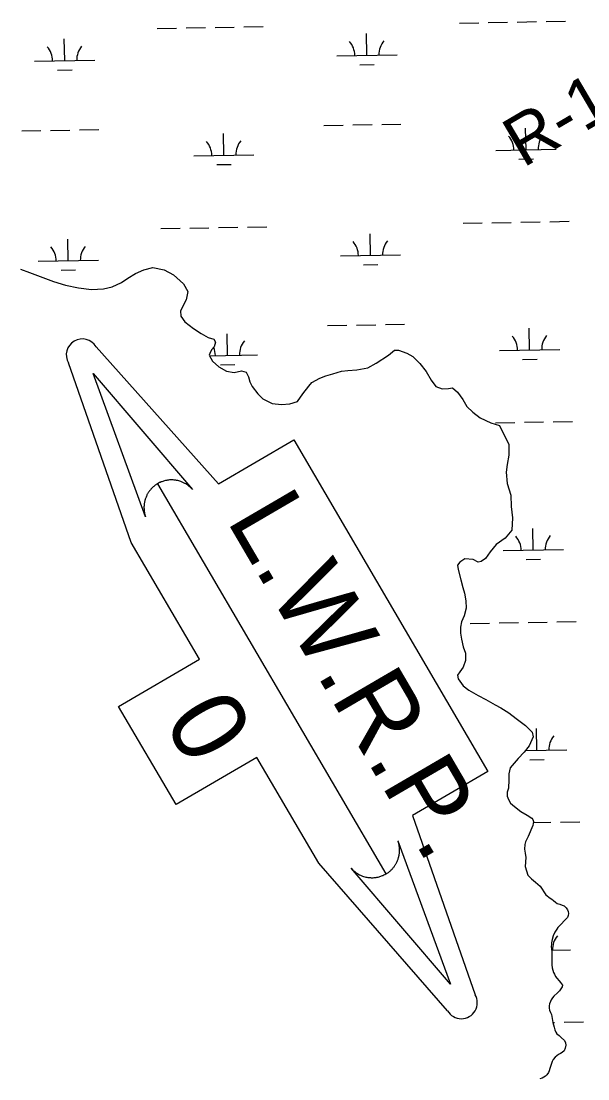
# Model space of a CAD drawing. Extents: x 3914892 to 3953151, y 242587 to 268572.
# Drawn here: x 3938068 to 3939009, y 249387 to 251144 of the extents above; entities that cross this region are included whole.
import ezdxf

# ---------------------------------------------------------------- set-up
doc = ezdxf.new("R2010")
doc.units = 0
for name, color, linetype in [('V-RIVR-RANG-IDEN', 7, 'Continuous'), ('V-TOPO-WATR-IDEN', 7, 'Continuous'), ('V-WETL-SWMP', 7, 'Continuous')]:
    doc.layers.add(name, color=color, linetype=linetype)

msp = doc.modelspace()

# ---------------------------------------------------------------- linework, layer by layer
at = {"layer": 'V-TOPO-WATR-IDEN'}
msp.add_line((3938294.2, 250375.8), (3938673.3, 249727.2), dxfattribs=at)
for points in [[(3938191.9, 250603.2), (3938395.4, 250375.4), (3938520.4, 250448.4), (3938842.6, 249897.2), (3938717.6, 249824.1), (3938821.3, 249526.5)], [(3938775.5, 249499.8), (3938561.7, 249745.3), (3938459.1, 249920.9), (3938325, 249842.5), (3938229.5, 250005.7), (3938363.6, 250084.1), (3938250.2, 250278.2), (3938146.2, 250576.5)]]:
    msp.add_lwpolyline(points, dxfattribs=at)
for points in [[(3938274.3, 250320.7), (3938187, 250559.1), (3938352, 250366.1), (3938348.8, 250369.4), (3938345.5, 250372.3), (3938344.1, 250373.3), (3938342.8, 250374.2), (3938341.2, 250375.3), (3938339.6, 250376.2), (3938338.2, 250376.9), (3938336.3, 250377.9), (3938334.1, 250378.8), (3938332.9, 250379.3), (3938331.3, 250379.8), (3938329.2, 250380.4), (3938327.5, 250380.8), (3938325.7, 250381.2), (3938324.5, 250381.4), (3938323.2, 250381.6), (3938321.5, 250381.8), (3938320, 250381.9), (3938318.5, 250382), (3938317.3, 250382), (3938315.5, 250382), (3938313.7, 250381.9), (3938312.3, 250381.7), (3938310.7, 250381.5), (3938309.3, 250381.3), (3938308, 250381.1), (3938307.1, 250380.9), (3938305.6, 250380.5), (3938304.1, 250380.1), (3938302.7, 250379.6), (3938301.3, 250379.1), (3938300, 250378.6), (3938298.6, 250378), (3938297.5, 250377.5), (3938295.9, 250376.7), (3938294.2, 250375.8), (3938293.6, 250375.4), (3938292.8, 250374.9), (3938291.9, 250374.3), (3938291, 250373.7), (3938290.2, 250373.1), (3938289.4, 250372.5), (3938288.5, 250371.8), (3938287.8, 250371.3), (3938286.9, 250370.5), (3938286.1, 250369.7), (3938285.5, 250369.2), (3938284.1, 250367.7), (3938283.3, 250366.9), (3938282.8, 250366.4), (3938282.1, 250365.5), (3938281.4, 250364.6), (3938280.7, 250363.7), (3938279.9, 250362.6), (3938279.2, 250361.6), (3938278.6, 250360.7), (3938278.2, 250360), (3938277.6, 250359.1), (3938277.1, 250358.2), (3938276.5, 250357.1), (3938276, 250356), (3938275.5, 250354.9), (3938274.9, 250353.5), (3938274.5, 250352.4), (3938274.1, 250351.3), (3938273.7, 250350.1), (3938273.4, 250349.2), (3938273.1, 250348.2), (3938272.7, 250346.7), (3938272.7, 250346.6), (3938272.5, 250345.7), (3938272.4, 250345), (3938272.2, 250344), (3938272, 250342.7), (3938271.8, 250341.7), (3938271.7, 250340.8), (3938271.6, 250339.6), (3938271.6, 250338.5), (3938271.5, 250337.7), (3938271.5, 250336.6), (3938271.5, 250335.2), (3938271.6, 250334.3), (3938271.6, 250333.6), (3938271.6, 250333), (3938271.7, 250332.3), (3938271.8, 250331.3), (3938271.9, 250330.3), (3938272, 250329.3), (3938272.2, 250328.4), (3938272.4, 250327.2), (3938272.6, 250326.4), (3938272.9, 250325.3), (3938273.2, 250323.9), (3938273.5, 250322.9), (3938273.7, 250322.2), (3938274, 250321.5), (3938274.1, 250321)], [(3938693.2, 249782.3), (3938780.5, 249543.9), (3938615.5, 249736.9), (3938618.6, 249733.6), (3938622, 249730.7), (3938623.4, 249729.6), (3938624.7, 249728.7), (3938626.3, 249727.7), (3938627.9, 249726.8), (3938629.3, 249726), (3938631.2, 249725.1), (3938633.3, 249724.2), (3938634.6, 249723.7), (3938636.2, 249723.2), (3938638.3, 249722.5), (3938639.9, 249722.1), (3938641.8, 249721.8), (3938643, 249721.5), (3938644.3, 249721.4), (3938645.9, 249721.2), (3938647.4, 249721.1), (3938648.9, 249721), (3938650.2, 249721), (3938652, 249721), (3938653.7, 249721.1), (3938655.1, 249721.2), (3938656.8, 249721.4), (3938658.2, 249721.7), (3938659.4, 249721.9), (3938660.4, 249722.1), (3938661.9, 249722.5), (3938663.4, 249722.9), (3938664.8, 249723.3), (3938666.2, 249723.8), (3938667.4, 249724.4), (3938668.8, 249724.9), (3938670, 249725.5), (3938671.5, 249726.3), (3938673.3, 249727.2), (3938673.8, 249727.5), (3938674.6, 249728), (3938675.5, 249728.6), (3938676.4, 249729.2), (3938677.3, 249729.8), (3938678.1, 249730.4), (3938679, 249731.2), (3938679.6, 249731.7), (3938680.6, 249732.5), (3938681.4, 249733.3), (3938682, 249733.8), (3938683.4, 249735.2), (3938684.1, 249736), (3938684.6, 249736.6), (3938685.4, 249737.5), (3938686.1, 249738.4), (3938686.8, 249739.3), (3938687.6, 249740.4), (3938688.3, 249741.4), (3938688.8, 249742.2), (3938689.3, 249742.9), (3938689.9, 249743.9), (3938690.4, 249744.8), (3938690.9, 249745.9), (3938691.4, 249747), (3938692, 249748.1), (3938692.6, 249749.5), (3938693, 249750.5), (3938693.4, 249751.7), (3938693.8, 249752.8), (3938694.1, 249753.8), (3938694.3, 249754.8), (3938694.7, 249756.3), (3938694.7, 249756.4), (3938694.9, 249757.3), (3938695.1, 249757.9), (3938695.3, 249759), (3938695.5, 249760.2), (3938695.6, 249761.2), (3938695.7, 249762.2), (3938695.8, 249763.3), (3938695.9, 249764.5), (3938695.9, 249765.3), (3938695.9, 249766.3), (3938695.9, 249767.8), (3938695.9, 249768.7), (3938695.9, 249769.3), (3938695.8, 249770), (3938695.8, 249770.7), (3938695.7, 249771.7), (3938695.5, 249772.7), (3938695.4, 249773.6), (3938695.3, 249774.6), (3938695, 249775.8), (3938694.9, 249776.5), (3938694.6, 249777.7), (3938694.2, 249779), (3938694, 249780), (3938693.7, 249780.8), (3938693.5, 249781.5), (3938693.3, 249782)]]:
    msp.add_lwpolyline(points, close=True, dxfattribs=at)
for centre, start, end in [((3938169, 250589.8), 30.308, 210.308), ((3938798.4, 249513.1), 210.308, 30.308)]:
    msp.add_arc(centre, 26.5, start, end, dxfattribs=at)
at = {"layer": 'V-WETL-SWMP'}
for p, q in [((3938293.5, 251132.3), (3938325.5, 251132.9)), ((3938341.5, 251133.2), (3938373.5, 251133.7)), ((3938389.5, 251134), (3938421.5, 251134.6)), ((3938437.5, 251134.9), (3938469.5, 251135.5)), ((3938795.3, 251141.3), (3938827.3, 251141.9)), ((3938843.3, 251142.1), (3938875.3, 251142.7)), ((3938891.3, 251143), (3938923.3, 251143.6)), ((3938939.3, 251143.9), (3938971.3, 251144.4)), ((3938139.9, 251078.8), (3938139.2, 251114.8)), ((3938641.7, 251087.8), (3938641, 251123.8)), ((3938089.9, 251077.9), (3938189.8, 251079.7)), ((3938591.7, 251086.9), (3938691.7, 251088.7)), ((3938128.1, 251063.2), (3938152.1, 251063.6)), ((3938630, 251072.1), (3938654, 251072.6)), ((3938570.4, 250971.1), (3938602.3, 250971.6)), ((3938618.3, 250971.9), (3938650.3, 250972.5)), ((3938666.3, 250972.8), (3938698.3, 250973.4)), ((3938068.5, 250962.1), (3938100.5, 250962.7)), ((3938116.5, 250962.9), (3938148.5, 250963.5)), ((3938164.5, 250963.8), (3938196.5, 250964.4)), ((3938404.1, 250921.7), (3938403.5, 250957.6)), ((3938906, 250930.6), (3938905.3, 250966.6)), ((3938354.2, 250920.8), (3938454.1, 250922.5)), ((3938856, 250929.7), (3938956, 250931.5)), ((3938392.4, 250906), (3938416.4, 250906.4)), ((3938894.2, 250915), (3938918.2, 250915.4)), ((3938299.5, 250799.7), (3938331.5, 250800.3)), ((3938347.5, 250800.5), (3938379.5, 250801.1)), ((3938395.4, 250801.4), (3938427.4, 250802)), ((3938443.4, 250802.3), (3938475.4, 250802.8)), ((3938801.3, 250808.7), (3938833.3, 250809.2)), ((3938849.3, 250809.5), (3938881.3, 250810.1)), ((3938897.3, 250810.4), (3938929.3, 250811)), ((3938945.3, 250811.2), (3938977.3, 250811.8)), ((3938145.8, 250746.2), (3938145.2, 250782.2)), ((3938647.6, 250755.2), (3938647, 250791.2)), ((3938095.8, 250745.3), (3938195.8, 250747.1)), ((3938597.6, 250754.3), (3938697.6, 250756.1)), ((3938066.7, 250732.1), (3938081.5, 250727)), ((3938081.5, 250727), (3938099.2, 250720.3)), ((3938134.1, 250730.5), (3938158.1, 250731)), ((3938244.8, 250717.2), (3938257.7, 250725.2)), ((3938257.7, 250725.2), (3938271.1, 250731)), ((3938271.1, 250731), (3938286.2, 250734.9)), ((3938286.2, 250734.9), (3938304.8, 250731.4)), ((3938304.8, 250731.4), (3938320.6, 250723.1)), ((3938635.9, 250739.5), (3938659.9, 250740)), ((3938099.2, 250720.3), (3938121.3, 250711.7)), ((3938121.3, 250711.7), (3938141.2, 250705.7)), ((3938218.6, 250703), (3938234, 250710.1)), ((3938234, 250710.1), (3938244.8, 250717.2)), ((3938320.6, 250723.1), (3938337, 250708.1)), ((3938337, 250708.1), (3938344.4, 250695.3)), ((3938141.2, 250705.7), (3938162.7, 250701.2)), ((3938162.7, 250701.2), (3938184.6, 250698.7)), ((3938184.6, 250698.7), (3938204.5, 250699.7)), ((3938204.5, 250699.7), (3938218.6, 250703)), ((3938344.4, 250695.3), (3938341.8, 250681.2)), ((3938341.8, 250681.2), (3938332.3, 250663.2)), ((3938332.3, 250663.2), (3938332.9, 250653.9)), ((3938332.9, 250653.9), (3938339.4, 250644.9)), ((3938339.4, 250644.9), (3938353.8, 250633.7)), ((3938576.3, 250638.4), (3938608.3, 250639)), ((3938624.3, 250639.3), (3938656.3, 250639.9)), ((3938672.3, 250640.2), (3938704.3, 250640.7)), ((3938353.8, 250633.7), (3938366.4, 250625.4)), ((3938366.4, 250625.4), (3938377.9, 250618.7)), ((3938410.1, 250589), (3938409.5, 250625)), ((3938911.9, 250598), (3938911.3, 250634)), ((3938377.9, 250618.7), (3938387.3, 250615.8)), ((3938388.3, 250603.3), (3938383.8, 250598.2)), ((3938387.3, 250615.8), (3938390.5, 250611)), ((3938390.5, 250611), (3938388.3, 250603.3)), ((3938380.9, 250592.1), (3938379.9, 250589.5)), ((3938379.9, 250589.5), (3938385.4, 250579.6)), ((3938380.5, 250588.5), (3938460.1, 250589.9)), ((3938383.8, 250598.2), (3938380.9, 250592.1)), ((3938657.2, 250576.1), (3938677.3, 250589.2)), ((3938677.3, 250589.2), (3938687.6, 250597.8)), ((3938687.6, 250597.8), (3938693.9, 250597.9)), ((3938693.9, 250597.9), (3938707.9, 250592.8)), ((3938707.9, 250592.8), (3938717.8, 250587.2)), ((3938717.8, 250587.2), (3938729.7, 250575.4)), ((3938861.9, 250597.1), (3938961.9, 250598.9)), ((3938385.4, 250579.6), (3938395.7, 250570)), ((3938395.7, 250570), (3938408.6, 250562.6)), ((3938398.4, 250573.4), (3938422.4, 250573.8)), ((3938625.2, 250565), (3938643.1, 250568.4)), ((3938643.1, 250568.4), (3938657.2, 250576.1)), ((3938729.7, 250575.4), (3938740, 250562.1)), ((3938900.2, 250582.4), (3938924.2, 250582.8)), ((3938408.6, 250562.6), (3938421.4, 250560.7)), ((3938421.4, 250560.7), (3938433.6, 250563.3)), ((3938433.6, 250563.3), (3938441.3, 250561.1)), ((3938441.3, 250561.1), (3938445.2, 250553.4)), ((3938445.2, 250553.4), (3938447.1, 250545.1)), ((3938550.5, 250543.8), (3938563.4, 250551.3)), ((3938563.4, 250551.3), (3938573.6, 250554.8)), ((3938573.6, 250554.8), (3938585.2, 250558.5)), ((3938585.2, 250558.5), (3938599.5, 250563)), ((3938599.5, 250563), (3938609.8, 250563.9)), ((3938609.8, 250563.9), (3938625.2, 250565)), ((3938740, 250562.1), (3938748.3, 250548)), ((3938447.1, 250545.1), (3938451.3, 250537.2)), ((3938451.3, 250537.2), (3938460.8, 250525.1)), ((3938535.2, 250524.9), (3938545.5, 250538.1)), ((3938545.5, 250538.1), (3938550.5, 250543.8)), ((3938748.3, 250548), (3938756.3, 250537.4)), ((3938756.3, 250537.4), (3938766.8, 250533.5)), ((3938766.8, 250533.5), (3938777, 250534.1)), ((3938777, 250534.1), (3938783.8, 250534.9)), ((3938783.8, 250534.9), (3938792.2, 250527.7)), ((3938460.8, 250525.1), (3938469.1, 250516.6)), ((3938469.1, 250516.6), (3938484.4, 250509.2)), ((3938526.3, 250512.5), (3938535.2, 250524.9)), ((3938792.2, 250527.7), (3938800.9, 250515.8)), ((3938800.9, 250515.8), (3938807.6, 250504.2)), ((3938484.4, 250509.2), (3938500, 250507.1)), ((3938500, 250507.1), (3938513.8, 250508.3)), ((3938513.8, 250508.3), (3938526.3, 250512.5)), ((3938807.6, 250504.2), (3938817.6, 250494.8)), ((3938817.6, 250494.8), (3938830, 250485.2)), ((3938830, 250485.2), (3938847.7, 250476.9)), ((3938951.2, 250478.6), (3938983.2, 250479.2)), ((3938847.7, 250476.9), (3938862.1, 250472.3)), ((3938855.2, 250476.9), (3938887.2, 250477.5)), ((3938862.1, 250472.3), (3938877.6, 250440.9)), ((3938903.2, 250477.8), (3938935.2, 250478.3)), ((3938877.6, 250440.9), (3938877.5, 250422.9)), ((3938877.5, 250422.9), (3938874.7, 250407.9)), ((3938874.7, 250407.9), (3938872.9, 250394.9)), ((3938872.9, 250394.9), (3938874.7, 250375.9)), ((3938874.7, 250375.9), (3938880.6, 250356.8)), ((3938880.6, 250356.8), (3938881.3, 250337.8)), ((3938881.3, 250337.8), (3938883.3, 250318.9)), ((3938883.3, 250318.9), (3938882.1, 250298.7)), ((3938871.5, 250285.5), (3938856.1, 250274.5)), ((3938882.1, 250298.7), (3938871.5, 250285.5)), ((3938917.9, 250265.4), (3938917.2, 250301.4)), ((3938856.1, 250274.5), (3938846.2, 250262.3)), ((3938804.5, 250250.7), (3938795.9, 250245.5)), ((3938818.3, 250249.7), (3938804.5, 250250.7)), ((3938838.5, 250251.4), (3938831.2, 250246.2)), ((3938846.2, 250262.3), (3938838.5, 250251.4)), ((3938867.9, 250264.5), (3938967.9, 250266.3)), ((3938795.9, 250245.5), (3938792.4, 250240.6)), ((3938792.4, 250240.6), (3938793, 250232.9)), ((3938793, 250232.9), (3938797.4, 250216)), ((3938826.4, 250245.6), (3938818.3, 250249.7)), ((3938831.2, 250246.2), (3938826.4, 250245.6)), ((3938906.2, 250249.7), (3938930.1, 250250.2)), ((3938797.4, 250216), (3938801, 250203)), ((3938801, 250203), (3938803.9, 250193.7)), ((3938803.9, 250193.7), (3938805.9, 250180.9)), ((3938805.9, 250180.9), (3938806.5, 250169)), ((3938806.5, 250169), (3938803, 250156.2)), ((3938798.9, 250146.2), (3938797.3, 250137.6)), ((3938803, 250156.2), (3938798.9, 250146.2)), ((3938861.2, 250144.3), (3938893.2, 250144.9)), ((3938909.2, 250145.1), (3938941.2, 250145.7)), ((3938957.2, 250146), (3938989.2, 250146.6)), ((3938797.3, 250137.6), (3938797.3, 250127.6)), ((3938797.3, 250127.6), (3938798.7, 250117.4)), ((3938813.2, 250143.4), (3938845.2, 250144)), ((3938798.7, 250117.4), (3938801.6, 250104.8)), ((3938801.6, 250104.8), (3938805.5, 250094.3)), ((3938805.5, 250094.3), (3938805.5, 250081.8)), ((3938805.5, 250081.8), (3938801.7, 250070.8)), ((3938795.9, 250063.1), (3938792.1, 250057.5)), ((3938792.1, 250057.5), (3938793.4, 250051.7)), ((3938801.7, 250070.8), (3938795.9, 250063.1)), ((3938793.4, 250051.7), (3938801.4, 250039.8)), ((3938801.4, 250039.8), (3938810.7, 250032.8)), ((3938810.7, 250032.8), (3938826.5, 250023.9)), ((3938826.5, 250023.9), (3938839.3, 250017.2)), ((3938839.3, 250017.2), (3938854.8, 250008.5)), ((3938854.8, 250008.5), (3938864.1, 250003.4)), ((3938864.1, 250003.4), (3938877.3, 249994.8)), ((3938877.3, 249994.8), (3938889.8, 249985.5)), ((3938889.8, 249985.5), (3938904.9, 249974)), ((3938904.9, 249974), (3938915.9, 249963.1)), ((3938917.5, 249955.1), (3938911.4, 249940.3)), ((3938915.9, 249963.1), (3938917.5, 249955.1)), ((3938923.8, 249932.8), (3938923.2, 249968.8)), ((3938911.4, 249940.3), (3938902.8, 249929.4)), ((3938892.6, 249919.1), (3938886.2, 249911.4)), ((3938902.8, 249929.4), (3938892.6, 249919.1)), ((3938905.2, 249932.4), (3938973.8, 249933.7)), ((3938912.1, 249917.1), (3938936.1, 249917.6)), ((3938879.4, 249903.7), (3938877.2, 249893.4)), ((3938886.2, 249911.4), (3938879.4, 249903.7)), ((3938877.2, 249883.8), (3938876.6, 249870)), ((3938877.2, 249893.4), (3938877.2, 249883.8)), ((3938876.6, 249870), (3938874.7, 249863.2)), ((3938874.7, 249863.2), (3938874.7, 249856.5)), ((3938874.7, 249856.5), (3938876.7, 249850.7)), ((3938876.7, 249850.7), (3938879.9, 249844.9)), ((3938879.9, 249844.9), (3938887, 249839.2)), ((3938887, 249839.2), (3938897.3, 249831.2)), ((3938897.3, 249831.2), (3938907.9, 249824.8)), ((3938907.9, 249824.8), (3938915.3, 249820)), ((3938915.3, 249820), (3938917.2, 249817.5)), ((3938917.2, 249817.5), (3938918.2, 249814.2)), ((3938918.2, 249814.2), (3938917.2, 249807.8)), ((3938917.9, 249812.6), (3938947.1, 249813.1)), ((3938963.1, 249813.4), (3938995.1, 249814)), ((3938917.2, 249807.8), (3938909.3, 249789.2)), ((3938903.8, 249776), (3938903.2, 249768.6)), ((3938905.1, 249780.8), (3938903.8, 249776)), ((3938909.3, 249789.2), (3938905.1, 249780.8)), ((3938903.2, 249768.6), (3938904.5, 249761.6)), ((3938904.5, 249761.6), (3938905.5, 249754.5)), ((3938905.5, 249754.5), (3938904.3, 249739.4)), ((3938904.3, 249739.4), (3938909.1, 249725)), ((3938909.1, 249725), (3938915.2, 249718.9)), ((3938915.2, 249718.9), (3938921.6, 249713.5)), ((3938921.6, 249713.5), (3938929.4, 249707.1)), ((3938929.4, 249707.1), (3938938.7, 249692.7)), ((3938938.7, 249692.7), (3938946.1, 249687.1)), ((3938946.1, 249687.1), (3938948.6, 249685.1)), ((3938948.6, 249685.1), (3938951.3, 249682.9)), ((3938951.3, 249682.9), (3938954.6, 249680.5)), ((3938954.6, 249680.5), (3938957.7, 249678.3)), ((3938957.7, 249678.3), (3938962, 249676.8)), ((3938962, 249676.8), (3938965.7, 249675.5)), ((3938965.7, 249675.5), (3938969.1, 249674)), ((3938969.1, 249674), (3938972.6, 249670.9)), ((3938972.6, 249670.9), (3938974.9, 249667.8)), ((3938974.5, 249654.7), (3938972.1, 249651.8)), ((3938976, 249658.1), (3938974.5, 249654.7)), ((3938974.9, 249667.8), (3938976, 249664.7)), ((3938976, 249664.7), (3938976.7, 249661.6)), ((3938976.7, 249661.6), (3938976, 249658.1)), ((3938956.9, 249635.6), (3938953.8, 249630.2)), ((3938958.6, 249638), (3938956.9, 249635.6)), ((3938962.2, 249641.8), (3938958.6, 249638)), ((3938972.1, 249651.8), (3938962.2, 249641.8)), ((3938949.5, 249618.4), (3938948.4, 249612.9)), ((3938951.2, 249624.4), (3938949.5, 249618.4)), ((3938953.8, 249630.2), (3938951.2, 249624.4)), ((3938948, 249609.8), (3938947.8, 249606.7)), ((3938947.8, 249606.7), (3938948.2, 249602.3)), ((3938948.4, 249612.9), (3938948, 249609.8)), ((3938948.2, 249602.3), (3938948.7, 249598.5)), ((3938948.5, 249600.5), (3938979.8, 249601)), ((3938949, 249585.9), (3938948.6, 249582.5)), ((3938948.6, 249582.5), (3938948.6, 249575.9)), ((3938948.7, 249598.5), (3938948.7, 249594.3)), ((3938948.7, 249594.3), (3938949, 249590.5)), ((3938949, 249590.5), (3938949, 249585.9)), ((3938948.6, 249575.9), (3938949.3, 249571.4)), ((3938949.3, 249571.4), (3938950.4, 249567.2)), ((3938950.4, 249567.2), (3938951.6, 249563.7)), ((3938951.6, 249563.7), (3938953.2, 249560.4)), ((3938953.2, 249560.4), (3938954.9, 249556.9)), ((3938954.9, 249556.9), (3938957.2, 249554.2)), ((3938957.2, 249554.2), (3938960.8, 249549.8)), ((3938960.8, 249549.8), (3938963.2, 249546.7)), ((3938958, 249529.8), (3938952.3, 249524)), ((3938961.3, 249533), (3938958, 249529.8)), ((3938963.9, 249536.3), (3938961.3, 249533)), ((3938963.2, 249546.7), (3938966.6, 249542.3)), ((3938965.7, 249539.4), (3938963.9, 249536.3)), ((3938966.6, 249542.3), (3938965.7, 249539.4)), ((3938946.3, 249515.4), (3938945, 249511.6)), ((3938947.7, 249518.2), (3938946.3, 249515.4)), ((3938949.9, 249521.4), (3938947.7, 249518.2)), ((3938952.3, 249524), (3938949.9, 249521.4)), ((3938945, 249511.6), (3938944.4, 249508)), ((3938944.4, 249508), (3938944.4, 249504.3)), ((3938944.4, 249504.3), (3938945.1, 249500.9)), ((3938945.1, 249500.9), (3938946.5, 249496.7)), ((3938946.5, 249496.7), (3938948, 249493.4)), ((3938948, 249493.4), (3938948.7, 249490.1)), ((3938948.7, 249490.1), (3938949.4, 249487)), ((3938949.4, 249487), (3938949.9, 249483.9)), ((3938949.9, 249483.9), (3938950.5, 249480.6)), ((3938950.5, 249480.6), (3938951.5, 249476.6)), ((3938950.6, 249480.4), (3938953.1, 249480.5)), ((3938969.1, 249480.8), (3939001.1, 249481.3)), ((3938951.5, 249476.6), (3938952.6, 249472.8)), ((3938952.6, 249472.8), (3938953.7, 249468.2)), ((3938953.7, 249468.2), (3938955.3, 249464.4)), ((3938955.3, 249464.4), (3938957.3, 249461.6)), ((3938957.3, 249461.6), (3938960.7, 249458.9)), ((3938960.7, 249458.9), (3938964.2, 249455.6)), ((3938964.2, 249455.6), (3938969.6, 249450.3)), ((3938969.6, 249450.3), (3938971.6, 249446.6)), ((3938972.1, 249442.8), (3938971, 249437.7)), ((3938971.6, 249446.6), (3938972.1, 249442.8)), ((3938957.3, 249425), (3938954.5, 249422.5)), ((3938960, 249427), (3938957.3, 249425)), ((3938963.3, 249428.8), (3938960, 249427)), ((3938965.9, 249430.6), (3938963.3, 249428.8)), ((3938969, 249433.3), (3938965.9, 249430.6)), ((3938971, 249437.7), (3938969, 249433.3)), ((3938946.8, 249407), (3938945.5, 249403.9)), ((3938949.4, 249415.4), (3938946.8, 249407)), ((3938950.9, 249418.7), (3938949.4, 249415.4)), ((3938954.5, 249422.5), (3938950.9, 249418.7)), ((3938935.6, 249389.6), (3938932.5, 249388)), ((3938938, 249391.4), (3938935.6, 249389.6)), ((3938940.7, 249393.4), (3938938, 249391.4)), ((3938943.1, 249397), (3938940.7, 249393.4)), ((3938944.4, 249399.9), (3938943.1, 249397)), ((3938945.5, 249403.9), (3938944.4, 249399.9)), ((3938932.5, 249388), (3938929, 249386.7))]:
    msp.add_line(p, q, dxfattribs=at)
for centre, start, end in [((3938696.9, 251089.3), 140.2532, 181.7968), ((3938084.6, 251078.3), 0.2532, 41.7968), ((3938195.1, 251080.3), 140.2532, 181.7968), ((3938586.4, 251087.3), 0.2532, 41.7968), ((3938850.7, 250930.1), 0.2532, 41.7968), ((3938961.2, 250932.1), 140.2532, 181.7968), ((3938348.9, 250921.1), 0.2532, 41.7968), ((3938459.4, 250923.1), 140.2532, 181.7968), ((3938592.4, 250754.7), 0.2532, 41.7968), ((3938702.9, 250756.6), 140.2532, 181.7968), ((3938090.6, 250745.7), 0.2532, 41.7968), ((3938201, 250747.7), 140.2532, 181.7968), ((3938856.7, 250597.5), 0.2532, 41.7968), ((3938967.1, 250599.5), 140.2532, 181.7968), ((3938354.9, 250588.5), 0.2532, 22.8943), ((3938465.3, 250590.5), 140.2532, 181.7968), ((3938862.6, 250264.9), 0.2532, 41.7968), ((3938973.1, 250266.9), 140.2532, 181.7968), ((3938979, 249934.2), 140.2532, 181.7968), ((3938985, 249601.6), 140.2532, 181.7968)]:
    msp.add_arc(centre, 35.2, start, end, dxfattribs=at)

# ---------------------------------------------------------------- texts
at = {"layer": 'V-RIVR-RANG-IDEN'}
msp.add_text('R-1.7', height=83, rotation=30.4489, dxfattribs=at).set_placement((3938901, 250899.9))
at = {"layer": 'V-TOPO-WATR-IDEN'}
for s, rotation, p in [('L.W.R.P.', 300.308, (3938407.5, 250315.6)), ('0', 300.3081, (3938302.3, 249981.4))]:
    msp.add_text(s, height=124.5, rotation=rotation, dxfattribs=at).set_placement(p)

doc.saveas('drawing.dxf')
